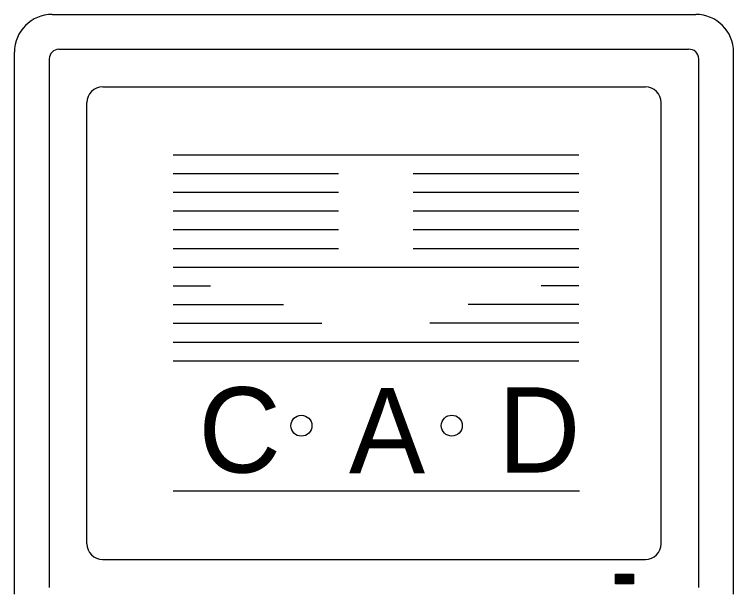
# Model space of a CAD drawing. Extents: x 22369.6 to 22428.3, y 22369.6 to 22415.
# Drawn here: x 22421.201 to 22422.873, y 22372.437 to 22373.771 of the extents above; entities that cross this region are included whole.
import ezdxf

# ---------------------------------------------------------------- set-up
doc = ezdxf.new("R2010")
doc.units = 0
for name, color, linetype in [('Level 2', 7, 'Continuous'), ('Level 3', 7, 'Continuous'), ('Level 5', 7, 'Continuous')]:
    doc.layers.add(name, color=color, linetype=linetype)

msp = doc.modelspace()

# ---------------------------------------------------------------- linework, layer by layer
at = {"layer": 'Level 2'}
for p, q in [((22421.4063, 22373.6025), (22422.6679, 22373.6025)), ((22421.3696, 22372.5393), (22421.3696, 22373.5658)), ((22422.7046, 22372.5393), (22422.7046, 22373.5658)), ((22421.4063, 22372.5026), (22422.6679, 22372.5026)), ((22422.5988, 22372.4681), (22422.6406, 22372.4681)), ((22422.5988, 22372.467), (22422.6406, 22372.467)), ((22422.5988, 22372.4656), (22422.6406, 22372.4656)), ((22422.5988, 22372.4641), (22422.6406, 22372.4641)), ((22422.5988, 22372.4628), (22422.6406, 22372.4628)), ((22422.5988, 22372.4616), (22422.6406, 22372.4616)), ((22422.5988, 22372.4603), (22422.6406, 22372.4603)), ((22422.5988, 22372.459), (22422.6406, 22372.459)), ((22422.5988, 22372.4576), (22422.6406, 22372.4576)), ((22422.5988, 22372.4563), (22422.6406, 22372.4563)), ((22422.5988, 22372.455), (22422.6406, 22372.455)), ((22422.5988, 22372.4536), (22422.6406, 22372.4536)), ((22422.5988, 22372.4525), (22422.6406, 22372.4525)), ((22422.5988, 22372.451), (22422.6406, 22372.451)), ((22422.5988, 22372.4496), (22422.6406, 22372.4496)), ((22422.5988, 22372.4485), (22422.6406, 22372.4485)), ((22422.5988, 22372.4471), (22422.6406, 22372.4471))]:
    msp.add_line(p, q, dxfattribs=at)
msp.add_lwpolyline([(22422.5988, 22372.4691), (22422.6406, 22372.4691), (22422.6406, 22372.446), (22422.5988, 22372.446)], close=True, dxfattribs=at)
for centre in [(22421.8683, 22372.8141), (22422.2179, 22372.8142)]:
    msp.add_circle(centre, 0.0244, dxfattribs=at)
for centre, start, end in [((22421.4062, 22373.5658), 90, 180), ((22422.6679, 22373.5658), 0, 90), ((22421.4062, 22372.5394), 180, 270), ((22422.6679, 22372.5394), 270, 0)]:
    msp.add_arc(centre, 0.0367, start, end, dxfattribs=at)
at = {"layer": 'Level 3'}
for p, q in [((22421.2891, 22373.771), (22422.7851, 22373.771)), ((22421.2011, 22372.4221), (22421.2011, 22373.683)), ((22421.3043, 22373.6898), (22422.7684, 22373.6898)), ((22422.8731, 22372.4221), (22422.8731, 22373.683)), ((22421.2823, 22372.4375), (22421.2823, 22373.6678)), ((22422.7919, 22372.4375), (22422.7919, 22373.6678))]:
    msp.add_line(p, q, dxfattribs=at)
for centre, radius, start, end in [((22421.289, 22373.6829), 0.088, 90, 180), ((22422.785, 22373.6829), 0.088, 0, 90), ((22421.3042, 22373.6678), 0.022, 90, 180), ((22422.7699, 22373.6678), 0.022, 0, 93.8704)]:
    msp.add_arc(centre, radius, start, end, dxfattribs=at)
at = {"layer": 'Level 5'}
for p, q in [((22421.5698, 22373.4446), (22422.5131, 22373.4446)), ((22421.5698, 22373.401), (22421.9543, 22373.401)), ((22422.1284, 22373.401), (22422.5131, 22373.401)), ((22421.5698, 22373.3575), (22421.9543, 22373.3575)), ((22422.1284, 22373.3575), (22422.5131, 22373.3575)), ((22421.5698, 22373.314), (22421.9543, 22373.314)), ((22422.1284, 22373.314), (22422.5131, 22373.314)), ((22421.5698, 22373.2703), (22421.9543, 22373.2703)), ((22422.1284, 22373.2703), (22422.5131, 22373.2703)), ((22421.5698, 22373.2266), (22421.9543, 22373.2266)), ((22422.1284, 22373.2266), (22422.5131, 22373.2266)), ((22421.5698, 22373.183), (22422.5131, 22373.183)), ((22421.5698, 22373.1396), (22421.6569, 22373.1396)), ((22422.5129, 22373.1396), (22422.4258, 22373.1396)), ((22421.5698, 22373.096), (22421.8268, 22373.096)), ((22422.5129, 22373.096), (22422.2559, 22373.096)), ((22421.5698, 22373.0525), (22421.9161, 22373.0525)), ((22422.5129, 22373.0525), (22422.1666, 22373.0525)), ((22421.5698, 22373.0088), (22422.5131, 22373.0088)), ((22421.5698, 22372.9651), (22422.5131, 22372.9651)), ((22421.5698, 22372.6626), (22422.5148, 22372.6626))]:
    msp.add_line(p, q, dxfattribs=at)

# ---------------------------------------------------------------- texts
for s, p in [('C', (22421.6289, 22372.7051)), ('A', (22421.9789, 22372.7035)), ('D', (22422.3253, 22372.7051))]:
    msp.add_text(s, height=0.1984, dxfattribs=at).set_placement(p)

doc.saveas('drawing.dxf')
